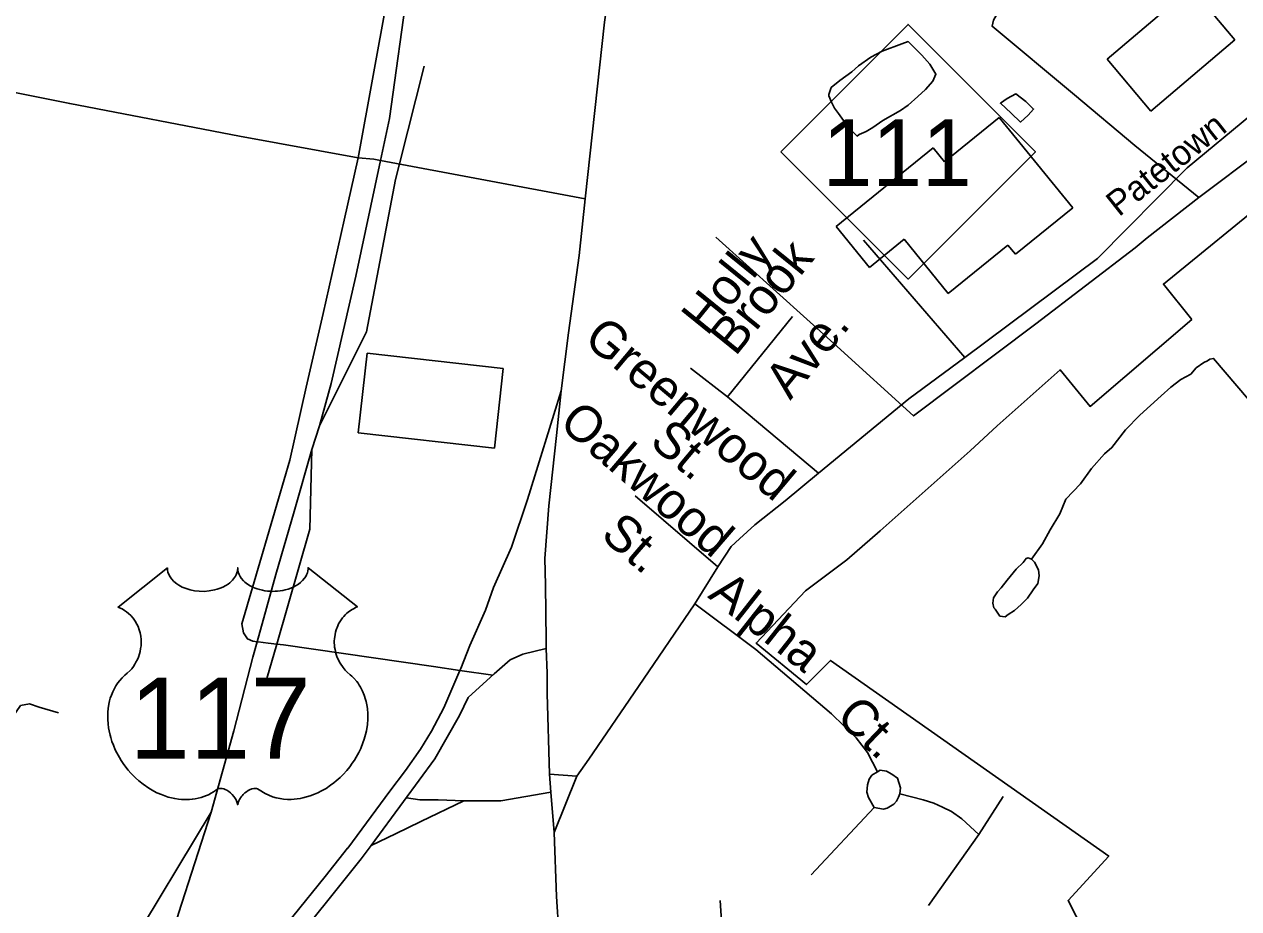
# Model space of a CAD drawing. Extents: x 2260773 to 2342389, y 552869 to 618546.
# Drawn here: x 2301642 to 2304816, y 605100 to 607413 of the extents above; entities that cross this region are included whole.
import ezdxf

# ---------------------------------------------------------------- set-up
doc = ezdxf.new("R2010")
doc.units = 0
for name, color, linetype in [('Exist Boundary Political City Limit New', 7, 'Continuous'), ('Exist Cultural Warehouse Building Footprint', 7, 'Continuous'), ('Exist Hydrographic Misc Water Feature', 7, 'Continuous'), ('Exist Railroad Mainline', 7, 'Continuous'), ('Exist Railroad Siding', 7, 'Continuous'), ('Exist Road Non-System Type 51', 7, 'Continuous'), ('Exist Road Non-System Type 51 Label', 7, 'Continuous'), ('Exist Road Primary NC Attributed', 7, 'Continuous'), ('Exist Road Primary NC Label', 7, 'Continuous'), ('Exist Road Primary NC Shield CELL', 7, 'Continuous'), ('Exist Road Primary NC Shield Number Label', 7, 'Continuous'), ('Exist Road Primary US Attributed', 7, 'Continuous'), ('Exist Road Primary US Divided Attributed', 7, 'Continuous'), ('Exist Road Primary US Shield CELL', 7, 'Continuous'), ('Exist Road Primary US Shield Number Label', 7, 'Continuous'), ('Exist Road Primary US UnDivided 4 Lane Attributed', 7, 'Continuous'), ('Exist Road Secondary Type 51 Attributed', 7, 'Continuous'), ('Map Preparation Boundary City Limit Buffer Line', 7, 'Continuous')]:
    doc.layers.add(name, color=color, linetype=linetype)

msp = doc.modelspace()

# ---------------------------------------------------------------- linework, layer by layer
at = {"layer": 'Exist Boundary Political City Limit New'}
for points in [[(2304693.5, 606640.8), (2304619.2, 606733.2), (2304907.8, 606968.4), (2305074.8, 607094.5), (2305199.8, 607043.9), (2305366.8, 607014.7), (2305656.5, 607014.7), (2305759.5, 607016.7), (2305911.5, 606958.1), (2305951.2, 606945.4), (2306068.5, 606902.5), (2306239.2, 606879.3), (2306598, 607040.2), (2306651.8, 606983.2), (2306725.5, 606795.6), (2306772.5, 606597.9), (2306796, 606480.6), (2306878, 606056.8), (2307023.8, 605650.9), (2307038, 605602.2), (2307173, 605332.5)], [(2304413, 605037.6), (2304370, 605121), (2304476.2, 605237.3), (2303749.2, 605748.9), (2303686, 605685.7), (2303554.5, 605794.4), (2303683.5, 605931), (2303792.2, 606011.9), (2303878.5, 606087.8), (2304113.8, 606296.8), (2304184.8, 606362.6), (2304349.2, 606509.2), (2304427.8, 606413.1), (2304693.5, 606640.8)]]:
    msp.add_lwpolyline(points, dxfattribs=at)
at = {"layer": 'Exist Cultural Warehouse Building Footprint'}
for p, q in [((2304681.3, 607519.4), (2304806.3, 607371.7)), ((2304472, 607321.1), (2304643.2, 607466)), ((2304806.3, 607371.7), (2304586.6, 607185.7)), ((2304586.6, 607185.7), (2304472, 607321.1)), ((2304047.4, 607053.3), (2304190.2, 607169.2)), ((2304190.2, 607169.2), (2304382.4, 606932.5)), ((2303764.2, 606884.1), (2304017.7, 607089.9)), ((2304017.7, 607089.9), (2304047.4, 607053.3)), ((2304382.4, 606932.5), (2304232.7, 606811)), ((2303851.2, 606776.9), (2303764.2, 606884.1)), ((2303942, 606850.6), (2303851.2, 606776.9)), ((2304057.1, 606708.7), (2303942, 606850.6)), ((2304213, 606835.3), (2304057.1, 606708.7)), ((2304232.7, 606811), (2304213, 606835.3)), ((2302514.8, 606344.1), (2302538.1, 606552.1)), ((2302538.1, 606552.1), (2302894, 606512.2)), ((2302894, 606512.2), (2302870.7, 606304.2)), ((2302870.7, 606304.2), (2302514.8, 606344.1))]:
    msp.add_line(p, q, dxfattribs=at)
at = {"layer": 'Exist Hydrographic Misc Water Feature'}
for points in [[(2304113.3, 607779), (2304195.7, 607715.8), (2304318.9, 607623.1), (2304302.7, 607593.1), (2304273.8, 607548.8), (2304237.9, 607504.3), (2304220.3, 607478.1), (2304200.6, 607453.9), (2304184.6, 607439.7), (2304175.2, 607423.7), (2304171.3, 607407.7), (2304387, 607228), (2304544.3, 607096), (2304711.6, 606959.7)], [(2303854.3, 607326.4), (2303884.2, 607342.6), (2303935.7, 607361.2), (2303951.7, 607367.3), (2303987.8, 607331.9), (2304008.5, 607308.1), (2304024.5, 607282.1), (2304016.9, 607264.3), (2303997, 607242.1), (2303977.3, 607223.6), (2303951.7, 607201.5), (2303931.8, 607187.4), (2303886.3, 607160.7), (2303860.2, 607142.7), (2303842.4, 607132.4), (2303824.3, 607124.1), (2303818.6, 607120.1), (2303794, 607145.7), (2303769.8, 607179.4), (2303760, 607193.5), (2303751.5, 607209.3), (2303745.2, 607225.2), (2303745, 607229.3), (2303750.9, 607247.1), (2303773.1, 607265.6), (2303804.9, 607288), (2303822.5, 607304), (2303854.3, 607326.4)], [(2304211.1, 607218.4), (2304233.2, 607230.5), (2304259.3, 607210.7), (2304279.8, 607191), (2304265.6, 607174.9), (2304245.9, 607156.8), (2304221.3, 607180.3), (2304193.4, 607206), (2304211.1, 607218.4)], [(2304711.6, 606959.7), (2304876.3, 607083.3)], [(2303449.5, 606856.2), (2303766.5, 606570), (2303966.2, 606388.2), (2304285.7, 606629.3), (2304545.3, 606828.2), (2304576.9, 606854.3), (2304711.6, 606959.7)], [(2304274.2, 606013.7), (2304303.3, 606054), (2304323.4, 606090.3), (2304348.7, 606132.3), (2304364.4, 606170.5), (2304402.2, 606210.6), (2304431.5, 606251.2), (2304464.9, 606289.6), (2304484.6, 606305.7), (2304520.5, 606352.2), (2304557.8, 606390.4), (2304613.4, 606440.8), (2304638.8, 606463.3), (2304664.8, 606483.8), (2304690.5, 606497.7), (2304704.6, 606513.9), (2304724.5, 606528.3), (2304734.4, 606532.1), (2304740.3, 606536.5), (2304750.4, 606538.6), (2304841.4, 606431.6)], [(2304274.2, 606013.7), (2304282.2, 606005.6), (2304292.5, 605985.9), (2304294.5, 605969.8), (2304290.8, 605950), (2304279.1, 605933.5), (2304263.6, 605911.5), (2304247.2, 605895.3), (2304229.7, 605879.3), (2304213.5, 605869.2), (2304205.7, 605863.1), (2304192, 605864.7), (2304179.7, 605882.8), (2304175.6, 605886.7), (2304173.3, 605898.8), (2304175.4, 605912.7), (2304185.2, 605928.6), (2304195.1, 605938.9), (2304210.7, 605958.8), (2304234.4, 605987.3), (2304252.3, 606005.3), (2304260.1, 606015.5), (2304265.8, 606017.4), (2304274.2, 606013.7)]]:
    msp.add_lwpolyline(points, dxfattribs=at)
at = {"layer": 'Exist Railroad Mainline'}
msp.add_line((2302413.1, 606362.9), (2302393.8, 606300.7), dxfattribs=at)
for points in [[(2302781.2, 609501.2), (2302780.6, 609175.3), (2302778.4, 609081.4), (2302778.2, 609070.3), (2302772.4, 608817.4), (2302760.2, 608473.5), (2302744.5, 608251.4), (2302713.4, 607987.2), (2302646.5, 607524.8), (2302596.4, 607166.3), (2302573.1, 607056.5)], [(2302573.1, 607056.5), (2302508.9, 606753.6), (2302443.8, 606473.1), (2302413.1, 606362.9)], [(2302393.8, 606300.7), (2302347.5, 606138.2), (2302299.4, 605973.8), (2302250.9, 605797.8), (2302239.7, 605757.3), (2302189.7, 605564.8), (2302130.1, 605352.4)], [(2302130.1, 605352.4), (2301910.2, 604986.2), (2301845.3, 604885.5), (2301733, 604728.3), (2301531.9, 604468.3), (2301466.5, 604389.2)], [(2302130.1, 605352.4), (2302045, 605087.4), (2301936.5, 604713.9), (2301894.7, 604570.2)]]:
    msp.add_lwpolyline(points, dxfattribs=at)
at = {"layer": 'Exist Railroad Siding'}
msp.add_line((2302686.9, 607303.4), (2302622.5, 607047.8), dxfattribs=at)
for points in [[(2302622.5, 607047.8), (2302612.1, 607006.7), (2302557.1, 606718.2), (2302536.4, 606608.1), (2302413.1, 606362.9)], [(2302393.8, 606300.7), (2302388, 606092.6), (2302301.9, 605791.6), (2302276.2, 605701.8)]]:
    msp.add_lwpolyline(points, dxfattribs=at)
at = {"layer": 'Exist Road Non-System Type 51'}
for p, q in [((2302514.8, 607063.8), (2302596.7, 607516.1)), ((2304100.3, 606540.8), (2303835.2, 606847.9)), ((2303479.7, 606438.3), (2303649.4, 606648)), ((2303479.7, 606438.3), (2303383, 606513.2)), ((2303717.8, 606238.8), (2303479.7, 606438.3)), ((2303238.7, 606179.8), (2303454.4, 605994.1)), ((2302780.7, 605722.7), (2302711.4, 605732.8)), ((2302866.2, 605710.2), (2302780.7, 605722.7)), ((2303086.2, 605446.5), (2303014.7, 605451.8)), ((2302791, 605381.4), (2302678.7, 605327.4)), ((2304200.8, 605393.2), (2304136.8, 605293.3)), ((2303863.2, 605364.2), (2303698.8, 605187.8)), ((2304136.8, 605293.3), (2304004.9, 605107.7)), ((2303482.2, 604798.6), (2303461.1, 605120.9))]:
    msp.add_line(p, q, dxfattribs=at)
for points in [[(2302250.9, 605797.8), (2302239.2, 605799.3), (2302225.2, 605805.1), (2302214.9, 605820.9), (2302210.8, 605845), (2302261.9, 606020.2), (2302336.1, 606272.6), (2302378.5, 606463.4), (2302423, 606656.3), (2302478, 606900.2), (2302514.8, 607063.8)], [(2303871.7, 605457.8), (2303846.2, 605508), (2303816.6, 605546.1), (2303751.6, 605609.7), (2303553.8, 605777.9), (2303394.2, 605896.7)], [(2302301.9, 605791.6), (2302279.3, 605793.7), (2302253.3, 605797.5), (2302250.9, 605797.8)], [(2302711.4, 605732.8), (2302319.2, 605790.1), (2302301.9, 605791.6)], [(2301731.8, 605611.7), (2301681, 605626.6), (2301655.6, 605635.1), (2301632.3, 605630.8), (2301601.9, 605586.4), (2301596.2, 605554.5), (2301562.3, 605459.1), (2301520, 605387), (2301498.8, 605346.7), (2301479.7, 605242.8), (2301458.5, 605149.5), (2301435.2, 605013.8), (2301397.1, 604812.4), (2301369.5, 604668.2), (2301346.2, 604549.5), (2301331.4, 604483.8)], [(2303871.7, 605457.8), (2303878.6, 605461.7), (2303895.7, 605459.7), (2303909.4, 605451.4), (2303924.3, 605441.4), (2303932.4, 605415.8), (2303930.5, 605399.8)], [(2303871.7, 605457.8), (2303857.4, 605448.5), (2303850.5, 605438.5), (2303845.4, 605424), (2303843.9, 605404.6), (2303848.6, 605390.7), (2303863.2, 605364.2)], [(2302791, 605381.4), (2302839, 605381.4), (2302887.1, 605381.4), (2303018.4, 605404.1)], [(2303930.5, 605399.8), (2303926.7, 605391.3), (2303921.6, 605380.7), (2303914.5, 605372.8), (2303897.3, 605362.5), (2303887.3, 605360.1), (2303863.2, 605364.2)], [(2304136.8, 605293.3), (2304092.5, 605334.8), (2304065.2, 605353.7), (2304041.6, 605365), (2304019, 605375.3), (2303991.7, 605384.7), (2303930.5, 605399.8)], [(2302721.9, 605384.6), (2302675.5, 605384), (2302640.6, 605389.4)], [(2302791, 605381.4), (2302723.5, 605384.6), (2302721.9, 605384.6)], [(2302678.7, 605327.4), (2302612.5, 605295.5), (2302548.4, 605264.9)]]:
    msp.add_lwpolyline(points, dxfattribs=at)
at = {"layer": 'Exist Road Primary NC Attributed'}
msp.add_lwpolyline([(2303026.8, 605299.2), (2303086.2, 605446.5), (2303117.3, 605490.3), (2303247.3, 605681.1), (2303394.2, 605896.7), (2303454.4, 605994.1), (2303489.9, 606046.6), (2303511.7, 606066.9), (2303551.2, 606103.3), (2303630.5, 606166.1), (2303717.8, 606238.8), (2303953.6, 606433.4), (2304100.3, 606540.8), (2304447.2, 606800.5), (2304681.4, 607037.3), (2304847.5, 607174.8)], dxfattribs=at)
at = {"layer": 'Exist Road Primary NC Shield CELL'}
msp.add_lwpolyline([(2303618.9, 607079.2), (2303951.9, 607412.2), (2304284.9, 607079.2), (2303951.9, 606746.2)], close=True, dxfattribs=at)
at = {"layer": 'Exist Road Primary US Attributed'}
for points in [[(2303108.1, 606956.3), (2303158.7, 607418.2), (2303177.8, 607552.8), (2303194.8, 607702.3), (2303213.8, 607846.5), (2303230.8, 608041.6)], [(2303045.4, 606453.8), (2303064.2, 606605.7), (2303092, 606807.9), (2303108.1, 606956.3)], [(2303005.9, 605780.3), (2303005.9, 605801.1), (2303003.8, 605946.4), (2303002.5, 606015.4), (2303013.1, 606153.3), (2303033, 606337.6), (2303045.4, 606453.8)], [(2303026.8, 605299.2), (2303018.4, 605404.1), (2303014.7, 605451.8), (2303009, 605662.2), (2303008.5, 605715.2), (2303005.9, 605780.3)]]:
    msp.add_lwpolyline(points, dxfattribs=at)
at = {"layer": 'Exist Road Primary US Divided Attributed'}
for points in [[(2303045.4, 606453.8), (2302957.4, 606169.8), (2302915.4, 606044.8), (2302868.1, 605939.7), (2302847, 605880.3), (2302806.4, 605788.1), (2302782.8, 605727.5), (2302780.7, 605722.7), (2302738.6, 605624.6), (2302706.1, 605563.7), (2302677.4, 605516.7), (2302638.5, 605461.2), (2302597.2, 605406.8), (2302487.2, 605258), (2302486.9, 605257.7), (2302428.3, 605183.8), (2302343.9, 605079.3), (2302292.8, 605021.2), (2302235.6, 604950.7), (2302120.8, 604829.3), (2302018.4, 604702.4), (2301894.7, 604570.2)], [(2301864.1, 604475.6), (2301926.9, 604538.6), (2302052.4, 604672.8), (2302154.8, 604799.6), (2302269.6, 604920.9), (2302325.2, 604989.6), (2302326.6, 604991.4), (2302326.9, 604991.7), (2302327.2, 604992.1), (2302378.4, 605050.2), (2302463.5, 605155.6), (2302522.8, 605230.3), (2302548.4, 605264.9), (2302633.3, 605379.8), (2302633.4, 605380), (2302715.2, 605491.9), (2302779.4, 605605.2), (2302801.7, 605651.6), (2302870.3, 605713.9), (2302911.7, 605750.6), (2302945.2, 605764.9), (2303005.9, 605780.3)]]:
    msp.add_lwpolyline(points, dxfattribs=at)
at = {"layer": 'Exist Road Primary US Shield CELL'}
msp.add_lwpolyline([(2302015.9, 605991), (2302016.2, 605985.6), (2302017.5, 605979.3), (2302018.5, 605976.1), (2302021.4, 605969.8), (2302026.3, 605962.5), (2302033.1, 605955.2), (2302040.8, 605948.9), (2302045.9, 605945.6), (2302054.7, 605940.9), (2302064.7, 605936.7), (2302075.7, 605933.5), (2302087.1, 605931.2), (2302099.4, 605929.9), (2302111.7, 605929.6), (2302124.9, 605930.6), (2302139.5, 605933.4), (2302146.2, 605935.2), (2302153.7, 605937.8), (2302160.7, 605940.7), (2302168.4, 605944.8), (2302174.5, 605948.7), (2302179.4, 605952.2), (2302186.2, 605958.7), (2302191.6, 605965.5), (2302193.9, 605969.3), (2302195.9, 605972.9), (2302198.6, 605980.7), (2302199.3, 605984.1), (2302199.9, 605991.2), (2302200.3, 605985.3), (2302200.9, 605981.5), (2302201.9, 605977.9), (2302203.4, 605974), (2302206.2, 605968.5), (2302209.2, 605964), (2302215, 605957.2), (2302218.5, 605953.9), (2302221.8, 605951.2), (2302230.5, 605945.2), (2302240.7, 605940), (2302245.7, 605937.8), (2302250.9, 605936), (2302257.4, 605934), (2302264.2, 605932.4), (2302270.9, 605931.3), (2302277.7, 605930.3), (2302284.7, 605929.8), (2302290.4, 605929.6), (2302297.4, 605929.7), (2302303.8, 605930.1), (2302310.5, 605930.9), (2302317.7, 605932.1), (2302323.6, 605933.4), (2302331.3, 605935.4), (2302338.3, 605937.9), (2302344.5, 605940.6), (2302352.5, 605944.8), (2302358.9, 605948.8), (2302363.6, 605952.6), (2302369.2, 605957.8), (2302374.6, 605963.9), (2302377.7, 605968.4), (2302379.9, 605973), (2302381.9, 605977.9), (2302383.2, 605983.1), (2302383.8, 605987.5), (2302383.9, 605991.4), (2302512.5, 605888.9), (2302509.5, 605887.8), (2302502.5, 605884.3), (2302496.9, 605881.1), (2302488.1, 605874.8), (2302484.3, 605871.4), (2302480.5, 605867.9), (2302477, 605864.1), (2302473.9, 605860.5), (2302470.2, 605855.3), (2302466.9, 605850.2), (2302463.6, 605844.5), (2302461.2, 605839.5), (2302457.3, 605829.2), (2302455.4, 605822.6), (2302454.1, 605817.1), (2302452.6, 605805.6), (2302452.2, 605800.2), (2302452.2, 605794.8), (2302452.6, 605789.1), (2302453.1, 605783.6), (2302454.1, 605777.9), (2302455, 605772.9), (2302456.6, 605766.7), (2302458.9, 605759.6), (2302461.7, 605752.7), (2302467.6, 605741.5), (2302475.1, 605730.1), (2302480.5, 605723.7), (2302485.8, 605718.2), (2302493.8, 605711.6), (2302498, 605707.8), (2302503, 605702.8), (2302511, 605693.5), (2302514.3, 605689.1), (2302517.6, 605684.1), (2302520.6, 605679), (2302523.7, 605673.6), (2302526.1, 605668.8), (2302530.6, 605657.8), (2302533.9, 605647), (2302535.4, 605641.4), (2302537.8, 605628.8), (2302538.8, 605622.6), (2302539.7, 605610.3), (2302539.8, 605595.4), (2302538.6, 605581.2), (2302536, 605564.7), (2302533.8, 605554.9), (2302530.4, 605543.4), (2302527.1, 605533.4), (2302521.2, 605518.8), (2302516, 605508.1), (2302509.3, 605495.7), (2302504.7, 605488.2), (2302499.3, 605480.1), (2302492.5, 605470.8), (2302484.6, 605460.9), (2302475.1, 605450.5), (2302467.4, 605442.9), (2302457.4, 605433.9), (2302451.3, 605428.9), (2302442.7, 605422.3), (2302430.8, 605414.4), (2302419.1, 605407.7), (2302409.2, 605402.6), (2302400.4, 605398.8), (2302389, 605394.5), (2302370, 605389.2), (2302363.1, 605387.8), (2302354.9, 605386.6), (2302347.2, 605385.8), (2302339.8, 605385.3), (2302329.8, 605385.3), (2302319.8, 605386.1), (2302310.4, 605387.5), (2302300.6, 605389.5), (2302290.3, 605392.6), (2302281, 605396.2), (2302271.6, 605400.8), (2302255.7, 605410.9), (2302251.1, 605413.3), (2302248.5, 605414), (2302242.4, 605414.3), (2302236.6, 605413.1), (2302230.7, 605410.7), (2302227.1, 605408.8), (2302222.4, 605405.7), (2302218.7, 605402.8), (2302214.3, 605398.6), (2302211.3, 605395.1), (2302209, 605392.4), (2302204.5, 605385.3), (2302202.9, 605382), (2302201.2, 605377.7), (2302199.7, 605371.3), (2302197.7, 605379.3), (2302195.4, 605384.7), (2302192.6, 605389.2), (2302189.8, 605393.2), (2302185.3, 605398.4), (2302181.3, 605402.3), (2302176.4, 605406.2), (2302171.2, 605409.4), (2302167.1, 605411.5), (2302163.3, 605412.9), (2302158.7, 605414.1), (2302154.9, 605414.4), (2302151.8, 605414.3), (2302147.5, 605413.3), (2302141.7, 605409.1), (2302136.2, 605405.3), (2302130.2, 605401.6), (2302123, 605397.8), (2302117.8, 605395.4), (2302111.6, 605392.9), (2302104.3, 605390.5), (2302096.4, 605388.5), (2302088.2, 605386.9), (2302081.1, 605385.7), (2302073.4, 605385), (2302066.5, 605384.8), (2302059.3, 605384.9), (2302052.5, 605385.4), (2302044.7, 605386.1), (2302035, 605387.5), (2302026.9, 605389.4), (2302018.4, 605391.6), (2302009.7, 605394.4), (2302000.4, 605398), (2301988.7, 605403), (2301980.5, 605407.2), (2301967.7, 605414.6), (2301952.7, 605425), (2301941.3, 605434.2), (2301933, 605441.7), (2301920.8, 605454.2), (2301913.6, 605462.3), (2301902.3, 605476.9), (2301895.1, 605487.5), (2301890.4, 605495.2), (2301883.6, 605507.7), (2301879.8, 605515.5), (2301875, 605526.9), (2301871.1, 605537.3), (2301868, 605547.2), (2301866.2, 605553.5), (2301863.8, 605564.5), (2301862.3, 605572.3), (2301860.9, 605583.1), (2301860.1, 605594.4), (2301859.9, 605604.8), (2301860.2, 605613.5), (2301861.2, 605623.6), (2301862.9, 605634.3), (2301865, 605643.5), (2301866.8, 605650.1), (2301869.5, 605658.1), (2301873.2, 605667), (2301877.4, 605675.5), (2301881.5, 605682.6), (2301886.6, 605690.2), (2301891.6, 605696.7), (2301898.1, 605703.8), (2301905, 605710.3), (2301911.2, 605715.4), (2301918.7, 605722.7), (2301922.6, 605727.1), (2301927.2, 605733.3), (2301931, 605739), (2301933.9, 605744.1), (2301937.8, 605751.6), (2301940.2, 605757.2), (2301943.1, 605765.9), (2301944.6, 605772), (2301946.1, 605779.8), (2301947.1, 605787.2), (2301947.5, 605796.4), (2301947.3, 605804), (2301946.3, 605812.8), (2301944.6, 605821.4), (2301942.6, 605828.8), (2301939.4, 605837.3), (2301936.5, 605843.5), (2301931.6, 605852), (2301926.1, 605859.8), (2301920.4, 605866.2), (2301914.7, 605871.9), (2301909.3, 605876.1), (2301904.1, 605879.9), (2301897.5, 605883.8), (2301891.2, 605886.9), (2301887.3, 605888.5)], close=True, dxfattribs=at)
at = {"layer": 'Exist Road Primary US UnDivided 4 Lane Attributed'}
msp.add_lwpolyline([(2303094.1, 604249.4), (2303087.1, 604330.8), (2303080.1, 604464.3), (2303059.6, 604772), (2303045.5, 604943), (2303032.7, 605131.7), (2303026.8, 605299.2)], dxfattribs=at)
at = {"layer": 'Exist Road Secondary Type 51 Attributed'}
for points in [[(2302573.1, 607056.5), (2302555.7, 607059.5), (2302514.8, 607063.8), (2302204.4, 607120.2), (2301760.8, 607205.2), (2301372.1, 607283.2), (2300991.4, 607343.2), (2300723.5, 607379.8), (2300350.2, 607435.5), (2300073.5, 607473.6), (2299877.3, 607500), (2299662.1, 607516.6), (2299504.7, 607526.3), (2299403.7, 607530.7), (2299340.7, 607530.7), (2299273.4, 607532.2), (2299137.4, 607527.2), (2299130.2, 607526.9), (2298642.9, 607487.6), (2298315.5, 607460.1)], [(2303108.1, 606956.3), (2302573.1, 607056.5)]]:
    msp.add_lwpolyline(points, dxfattribs=at)
at = {"layer": 'Map Preparation Boundary City Limit Buffer Line'}
for points in [[(2304693.5, 606640.8), (2304619.2, 606733.2), (2304907.8, 606968.4), (2305074.8, 607094.5), (2305199.8, 607043.9), (2305366.8, 607014.7), (2305656.5, 607014.7), (2305759.5, 607016.7), (2305911.5, 606958.1), (2305951.2, 606945.4), (2306068.5, 606902.5), (2306239.2, 606879.3), (2306598, 607040.2), (2306651.8, 606983.2), (2306725.5, 606795.6), (2306772.5, 606597.9), (2306796, 606480.6), (2306878, 606056.8), (2307023.8, 605650.9), (2307038, 605602.2), (2307173, 605332.5)], [(2304413, 605037.6), (2304370, 605121), (2304476.2, 605237.3), (2303749.2, 605748.9), (2303686, 605685.7), (2303554.5, 605794.4), (2303683.5, 605931), (2303792.2, 606011.9), (2303878.5, 606087.8), (2304113.8, 606296.8), (2304184.8, 606362.6), (2304349.2, 606509.2), (2304427.8, 606413.1), (2304693.5, 606640.8)]]:
    msp.add_lwpolyline(points, dxfattribs=at)

# ---------------------------------------------------------------- texts
at = {"layer": 'Exist Road Non-System Type 51 Label'}
for s, rotation, p in [('Holly', 51.0185, (2303426.4, 606594.9)), ('Brook', 51.0185, (2303500.4, 606542.1)), ('Greenwood', 320.0408, (2303100.2, 606582.8)), ('Ave.', 51.0185, (2303643.9, 606427.6)), ('Oakwood', 319.2738, (2303035.8, 606363.4)), ('St.', 320.0408, (2303272.8, 606314.7)), ('St.', 319.2738, (2303145.1, 606071.6)), ('Alpha', 321.7953, (2303425.9, 605915)), ('Ct.', 316.2992, (2303759.7, 605596.7))]:
    msp.add_text(s, height=95, rotation=rotation, dxfattribs=at).set_placement(p)
at = {"layer": 'Exist Road Primary NC Label'}
msp.add_text('Patetown', height=65.62, rotation=38.4461, dxfattribs=at).set_placement((2304502.9, 606907.6))
at = {"layer": 'Exist Road Primary NC Shield Number Label'}
msp.add_text('111', height=175, dxfattribs=at).set_placement((2303728, 606989.4))
at = {"layer": 'Exist Road Primary US Shield Number Label'}
msp.add_text('117', height=212.5, dxfattribs=at).set_placement((2301917, 605491.7))

doc.saveas('drawing.dxf')
